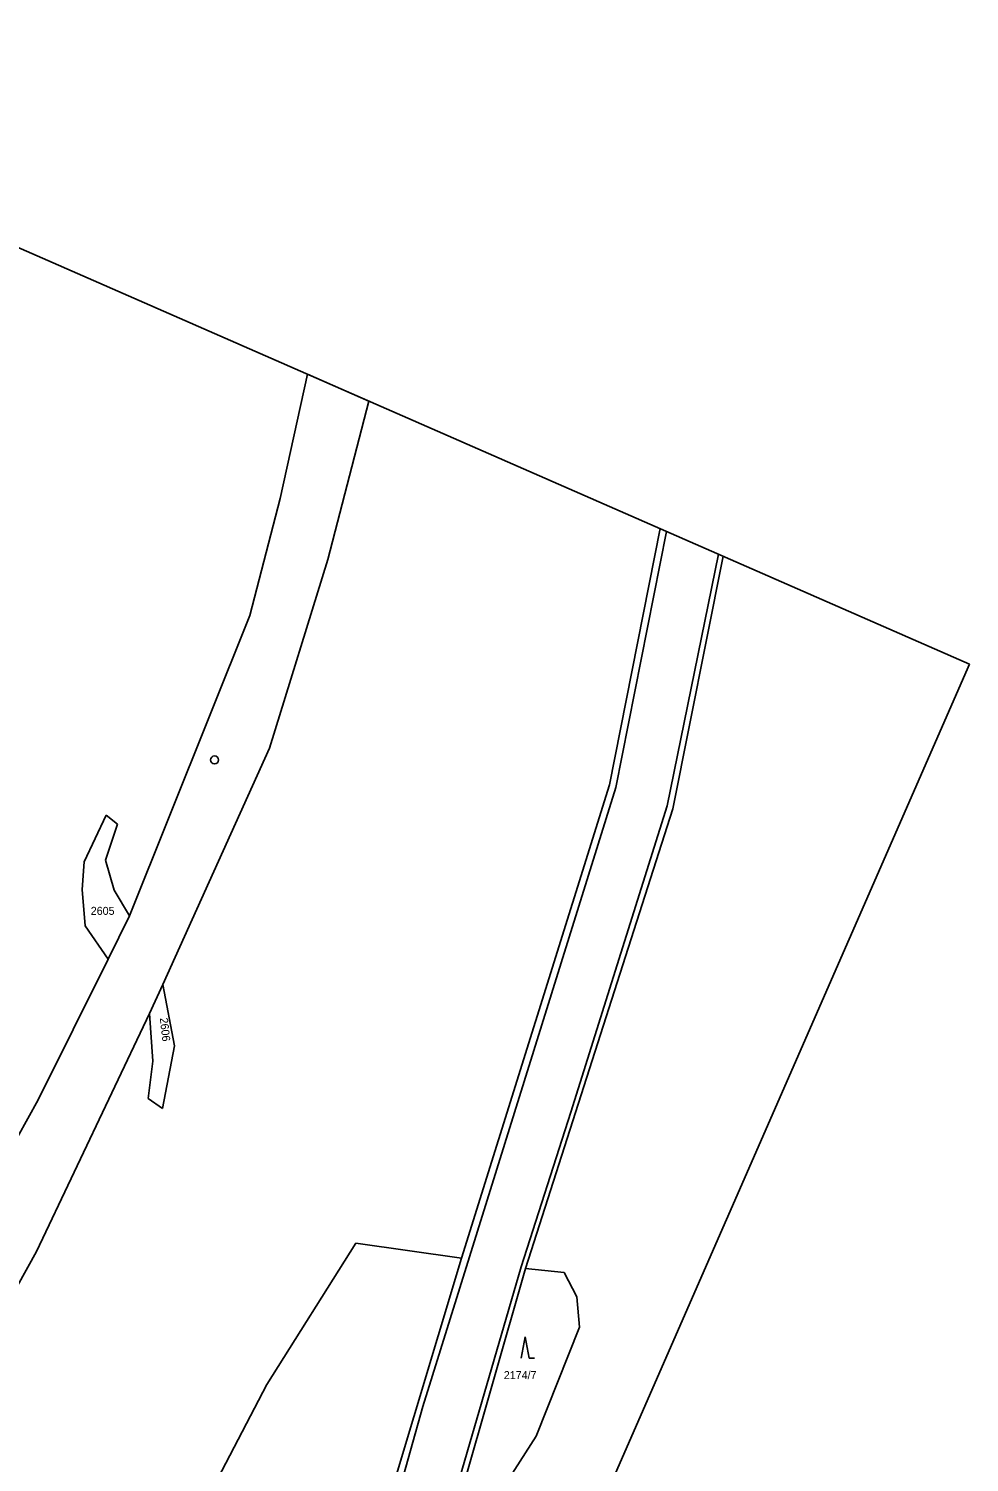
# Model space of a CAD drawing. Extents: x -806856 to -806332, y -1151642 to -1150946.
# Drawn here: x -806508 to -806331.6, y -1151214.9 to -1150946.2 of the extents above; entities that cross this region are included whole.
import ezdxf

# ---------------------------------------------------------------- set-up
doc = ezdxf.new("R2010")
doc.units = 0
for name, color, linetype in [('Default', 7, 'Continuous'), ('formát', 7, 'Continuous'), ('kilometráž - vrstava 7', 7, 'Continuous'), ('kn_celek - Cisla pozemkovych parcel', 7, 'Continuous'), ('kn_celek - Hranice parcel', 7, 'Continuous'), ('kn_celek - Vnitrni kresby', 7, 'Continuous'), ('kn_celek - Znacky kultur', 7, 'Continuous'), ('plochy - SZDC', 7, 'Continuous')]:
    doc.layers.add(name, color=color, linetype=linetype)

# ---------------------------------------------------------------- blocks, each defined once
blk = doc.blocks.new('308')
at = {"layer": 'Default'}
for p, q in [((-7.5, 0.2), (0, 40.2)), ((0, 40.2), (7.5, 0.2)), ((7.5, 0.2), (17.5, 0.2))]:
    blk.add_line(p, q, dxfattribs=at)

msp = doc.modelspace()

# ---------------------------------------------------------------- linework, layer by layer
at = {"layer": 'formát'}
for p, q in [((-806603.71, -1150946.22), (-806331.63, -1151065.3)), ((-806331.63, -1151065.3), (-806415.83, -1151257.68))]:
    msp.add_line(p, q, dxfattribs=at)
at = {"layer": 'kilometráž - vrstava 7'}
msp.add_circle((-806473.16, -1151083.27), 0.75, dxfattribs=at)
at = {"layer": 'kn_celek - Hranice parcel'}
for p, q in [((-806455.74, -1151010.98), (-806460.86, -1151034.28)), ((-806451.94, -1151045.73), (-806444.23, -1151016.01)), ((-806460.86, -1151034.28), (-806466.55, -1151056.22)), ((-806399.13, -1151087.92), (-806389.62, -1151039.92)), ((-806462.86, -1151081.06), (-806451.94, -1151045.73)), ((-806387.22, -1151092.44), (-806377.8, -1151045.09)), ((-806466.55, -1151056.22), (-806489.08, -1151112.47)), ((-806482.86, -1151125.33), (-806462.86, -1151081.06)), ((-806426.85, -1151176.65), (-806399.13, -1151087.92)), ((-806414.88, -1151178.55), (-806387.22, -1151092.44)), ((-806497.61, -1151102.34), (-806493.48, -1151093.6)), ((-806491.35, -1151095.33), (-806493.61, -1151102.03)), ((-806493.48, -1151093.6), (-806491.35, -1151095.33)), ((-806497.97, -1151107.57), (-806497.61, -1151102.34)), ((-806493.61, -1151102.03), (-806492.01, -1151107.67)), ((-806497.43, -1151114.33), (-806497.97, -1151107.57)), ((-806492.01, -1151107.67), (-806489.08, -1151112.47)), ((-806493.12, -1151120.59), (-806497.43, -1151114.33)), ((-806489.08, -1151112.47), (-806493.12, -1151120.59)), ((-806493.12, -1151120.59), (-806506.25, -1151146.99)), ((-806485.36, -1151130.76), (-806482.86, -1151125.33)), ((-806480.64, -1151136.87), (-806482.86, -1151125.33)), ((-806506.53, -1151175.36), (-806485.36, -1151130.76)), ((-806485.36, -1151130.76), (-806484.75, -1151139.73)), ((-806482.92, -1151148.56), (-806480.64, -1151136.87)), ((-806484.75, -1151139.73), (-806485.62, -1151146.7)), ((-806485.62, -1151146.7), (-806482.92, -1151148.56)), ((-806506.25, -1151146.99), (-806542.64, -1151212.58)), ((-806525.91, -1151210.3), (-806506.53, -1151175.36)), ((-806446.68, -1151173.85), (-806463.36, -1151200.29)), ((-806426.85, -1151176.65), (-806446.68, -1151173.85)), ((-806447.38, -1151244.82), (-806426.85, -1151176.65)), ((-806432.32, -1151239.57), (-806414.88, -1151178.55)), ((-806414.88, -1151178.55), (-806407.59, -1151179.35)), ((-806407.59, -1151179.35), (-806405.25, -1151183.88)), ((-806405.25, -1151183.88), (-806404.72, -1151189.55)), ((-806404.72, -1151189.55), (-806412.88, -1151210.03)), ((-806463.36, -1151200.29), (-806477.54, -1151227.46)), ((-806412.88, -1151210.03), (-806432.75, -1151241.03))]:
    msp.add_line(p, q, dxfattribs=at)
at = {"layer": 'kn_celek - Vnitrni kresby'}
for p, q in [((-806388.4, -1151040.45), (-806397.9, -1151088.41)), ((-806388.26, -1151091.88), (-806378.68, -1151044.71)), ((-806397.9, -1151088.41), (-806434.09, -1151204.41)), ((-806406.37, -1151149.26), (-806388.26, -1151091.88)), ((-806415.66, -1151178.27), (-806406.37, -1151149.26)), ((-806433.94, -1151240.84), (-806415.66, -1151178.27)), ((-806434.09, -1151204.41), (-806467.83, -1151323.67))]:
    msp.add_line(p, q, dxfattribs=at)
at = {"layer": 'plochy - SZDC'}
for p, q in [((-806455.74, -1151010.98), (-806460.86, -1151034.28)), ((-806444.23, -1151016.01), (-806455.74, -1151010.98)), ((-806451.94, -1151045.73), (-806444.23, -1151016.01)), ((-806460.86, -1151034.28), (-806466.55, -1151056.22)), ((-806462.86, -1151081.06), (-806451.94, -1151045.73)), ((-806466.55, -1151056.22), (-806489.08, -1151112.47)), ((-806482.86, -1151125.33), (-806462.86, -1151081.06)), ((-806489.08, -1151112.47), (-806493.12, -1151120.59)), ((-806493.12, -1151120.59), (-806506.25, -1151146.99)), ((-806485.36, -1151130.76), (-806482.86, -1151125.33)), ((-806506.53, -1151175.36), (-806485.36, -1151130.76)), ((-806506.25, -1151146.99), (-806542.64, -1151212.58)), ((-806525.91, -1151210.3), (-806506.53, -1151175.36))]:
    msp.add_line(p, q, dxfattribs=at)

# ---------------------------------------------------------------- block references
at = {"layer": 'kn_celek - Znacky kultur', "xscale": 0.1, "yscale": 0.10000000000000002}
msp.add_blockref('308', (-806414.92, -1151195.39), dxfattribs=at)

# ---------------------------------------------------------------- texts
at = {"layer": 'kn_celek - Cisla pozemkovych parcel'}
for s, p in [('2605', (-806496.37, -1151112.3)), ('2174/7', (-806418.92, -1151199.3))]:
    msp.add_text(s, height=1.5, dxfattribs=at).set_placement(p)
msp.add_text('2606', height=1.5, rotation=276.3857, dxfattribs=at).set_placement((-806483.42, -1151131.66))

doc.saveas('drawing.dxf')
